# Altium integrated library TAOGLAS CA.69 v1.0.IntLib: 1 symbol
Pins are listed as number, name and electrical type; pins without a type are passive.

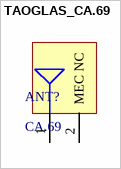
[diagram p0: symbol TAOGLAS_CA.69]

## TAOGLAS_CA.69
designator ANT?, comment CA.69
25.2*5.1*0.8mm CA.69 169MHz 7dBi Polymer Substrate Chip Antenna; ComponentLibStatus: Created; MFG: Taoglas; Temp_High: +85C; Temp_Low: -40C
footprint TAOGLAS_CA.69 (25.2*5.1*0.8mm CA.69 169MHz 7dBi Polymer Substrate Chip Antenna)
pins: 1 RF FEED, 2 MEC NC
